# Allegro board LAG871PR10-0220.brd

Outline 317.5 x 114.3 mm; copper layers: TOP, GND1, IN1, GND2, IN2, IN3, VCC, IN4, GND3, BOTTOM. Coordinates in mm from the lower left corner of the outline.

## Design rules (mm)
net group 10: nets +MIC2-VREFO-L +MIC2-VREFO-R
net group ASYN_12: nets H_CPUPWRGD H_CPUPWRGD_R
net group BC BUS_12/15: nets BC_CLK_ECE1117 BC_DAT_ECE1117
net group DDRB_CKE: nets DDR_B_CKE0 DDR_B_CKE1
net group DIFFPAIR1: nets UPD1_SMBCLK UPD1_SMBDAT
net group ISH_I2C1_ALS_SCL: nets ISH_I2C1_ALS_SCL ISH_I2C1_ALS_SDA
net group ISUM_SA: nets ISUMN_SA ISUMP_SA
net group ISUMN_GT: nets ISUMN_GT ISUMP_GT
net group MIPI: nets WWAN_MIPI_ANT_CLK WWAN_MIPI_ANT_DAT
net group PCIE_PRX_C_DTX_9: nets PCIE_PRX_C_DTX_N9 PCIE_PRX_C_DTX_P9
net group PCIE_PRX_DTX_13: nets PCIE_PRX_DTX_N13 PCIE_PRX_DTX_P13
net group PCIE_PRX_DTX_14: nets PCIE_PRX_DTX_N14 PCIE_PRX_DTX_P14
net group PCIE_PRX_DTX_15: nets PCIE_PRX_DTX_N15 PCIE_PRX_DTX_P15
net group PCIE_PRX_DTX_16: nets PCIE_PRX_DTX_N16 PCIE_PRX_DTX_P16
net group PCIE_PTX_C_DRX_13: nets PCIE_PTX_C_DRX_N13 PCIE_PTX_C_DRX_P13
net group PCIE_PTX_C_DRX_14: nets PCIE_PTX_C_DRX_N14 PCIE_PTX_C_DRX_P14
net group PCIE_PTX_C_DRX_15: nets PCIE_PTX_C_DRX_N15 PCIE_PTX_C_DRX_P15
net group PCIE_PTX_C_SW_DRX_12: nets PCIE_PTX_C_DRX_N11 PCIE_PTX_C_DRX_P11
net group PCIE_PTX_DRX_13: nets PCIE_PTX_DRX_N13 PCIE_PTX_DRX_P13
net group PCIE_PTX_DRX_14: nets PCIE_PTX_DRX_N14 PCIE_PTX_DRX_P14
net group PCIE_PTX_DRX_15: nets PCIE_PTX_DRX_N15 PCIE_PTX_DRX_P15
net group PCIE_PTX_DRX_16: nets PCIE_PTX_DRX_N16 PCIE_PTX_DRX_P16
net group PECI: nets PECI_EC PECI_EC_R
net group RTC_RTCX_20_70: nets PCH_RTCX1 PCH_RTCX2
net group SATA: nets PCIE_PTX_C_DRX_N16 PCIE_PTX_C_DRX_P16
net group SENSE_25: nets VCCIO_SENSE VSSIO_SENSE
net group TS_I2C_SCL: nets TS_I2C_SCL TS_I2C_SDA
net group USB3_PRX_DTX_P4: nets USB3_PRX_DTX_N4 USB3_PRX_DTX_P4
net group USB20_9_FP: nets USB20_N9_FP USB20_P9_FP
net group 5: nets ESPI_ALERT# ESPI_CS# ESPI_IO0 ESPI_IO0_R ESPI_IO1 ESPI_IO1_R ESPI_IO2 ESPI_IO2_R ESPI_IO3 ESPI_IO3_R ESPI_RESET#
net group 15: nets ESPI_CLK ESPI_CLK_5105 PCH_RTCRST# SRTCRST# TBT_ROM_CLK TBTA_ROM_CLK_PD
net group AR-HDMI: nets AR_DP1_N0 AR_DP1_N1 AR_DP1_N2 AR_DP1_N3 AR_DP1_P0 AR_DP1_P1 AR_DP1_P2 AR_DP1_P3 HDMI_CLKN HDMI_CLKP HDMI_L_CLKN HDMI_L_CLKP HDMI_L_TX_N0 HDMI_L_TX_N1 HDMI_L_TX_N2 HDMI_L_TX_P0 HDMI_L_TX_P1 HDMI_L_TX_P2 HDMI_TX_N0 HDMI_TX_N1 HDMI_TX_N2 HDMI_TX_P0 HDMI_TX_P1 HDMI_TX_P2
net group ASYN-COMP: nets CFG_RCOMP CPU_POPIRCOMP EDP_COMP EDRAM_OPIO_RCOMP EMMC_RCOMP EOPIO_RCOMP PCH_POPIRCOMP PCIE_RCOMPN PCIE_RCOMPP SD_RCOMP SM_RCOMP0 SM_RCOMP1 SM_RCOMP2 USBCOMP
net group ASYNCHRONOUS: nets +DDR_VREF_B_DQ +DDR_VREF_CA DDR_DRAMRST# DDR_DRAMRST#_R H_CATERR# H_VCCST_PWRGD_XDP PCH_PLTRST# PCH_PLTRST#_AND PLTRST_TPM# PROCHOT# PROCHOT#_R PROCHOT#_R1 VCCST_PWRGD VCCST_PWRGD_CPU XDP_OBS0 XDP_OBS0_R XDP_OBS1 XDP_OBS1_R XDP_OBS2_R XDP_OBS3_R
net group CARD READER: nets SD/MMCDAT0/RCLK+ SD/MMCDAT0/RCLK+_R SD/MMCDAT1/RCLK- SD/MMCDAT1/RCLK-_R SD_UHS2_D0N SD_UHS2_D0P SD_UHS2_D1N SD_UHS2_D1P
net group CARD-S_12: nets SD/MMCCD# SD/MMCCLK SD/MMCCLK_R SD/MMCCMD SD/MMCCMD_R SD/MMCDAT2 SD/MMCDAT2_R SD/MMCDAT3 SD/MMCDAT3_R SDWP
net group CLK-S_15: nets CPU_XDP_TCLK DMIC_CLK0 HDA_BIT_CLK HDA_BIT_CLK_R JTAG_CLK MSCLK PCH_JTAG_TCK SUSCLK SUSCLK_R WIGIG_32KHZ XCLK_BIASREF XDP_JTAGX
net group CNV-SINGLE: nets CLKREQ_CNV# CNV_BRI_PRX_DTX CNV_BRI_PTX_DRX CNV_BRI_PTX_DRX_R CNV_COEX1 CNV_COEX2 CNV_COEX3 CNV_DET#_EC CNV_RF_RESET# CNV_RGI_PRX_DTX CNV_RGI_PTX_DRX CNV_RGI_PTX_DRX_R CNV_WT_RCOMP
net group CNVI: nets CLK_CNV_PRX_DTX_N CLK_CNV_PRX_DTX_P CLK_CNV_PTX_DRX_N CLK_CNV_PTX_DRX_P CNV_PRX_DTX_N0 CNV_PRX_DTX_N1 CNV_PRX_DTX_P0 CNV_PRX_DTX_P1 CNV_PTX_DRX_N0 CNV_PTX_DRX_N1 CNV_PTX_DRX_P0 CNV_PTX_DRX_P1
net group CODEC: nets AUD_HP_NB_SENSE AUD_HP_OUT_L AUD_HP_OUT_L1 AUD_HP_OUT_R AUD_HP_OUT_R1 AUD_SENSE_A HP_OUT_L HP_OUT_R INT_SPK_L+ INT_SPK_L- INT_SPK_R+ INT_SPK_R- INT_SPKR_L+ INT_SPKR_L- INT_SPKR_R+ INT_SPKR_R- RING2 RING2_R SLEEVE SLEEVE_R
net group CONTROL LINK: nets PCH_CL_CLK1 PCH_CL_DATA1 PCH_CL_RST1#
net group CRITICAL LOW: nets H_THERMTRIP# INTRUDER# PCH_DPWROK PCH_DPWROK_EC PCH_PCIE_WAKE# PCH_RSMRST# PCH_RSMRST#_AND RESET_OUT RESET_OUT#_R SIO_PWRBTN# SVID_ALERT#_PWR_CPU SVID_CLK_PWR_CPU SVID_DAT_PWR_CPU SYS_PWROK SYS_RESET# THERMTRIP2# XDP_DBRESET#
net group CRITICAL S_15: nets PCH_PWROK PCIE_WAKE# PCIE_WAKE#_R
net group DDI1: nets CPU_DP1_AUXN CPU_DP1_AUXN_C CPU_DP1_AUXP CPU_DP1_AUXP_C CPU_DP1_N0 CPU_DP1_N0_C CPU_DP1_N1 CPU_DP1_N1_C CPU_DP1_N2 CPU_DP1_N2_C CPU_DP1_N3 CPU_DP1_N3_C CPU_DP1_P0 CPU_DP1_P0_C CPU_DP1_P1 CPU_DP1_P1_C CPU_DP1_P2 CPU_DP1_P2_C CPU_DP1_P3 CPU_DP1_P3_C
net group DDI2: nets CPU_DP2_AUXN CPU_DP2_AUXN_C CPU_DP2_AUXP CPU_DP2_AUXP_C CPU_DP2_N0 CPU_DP2_N0_C CPU_DP2_N1 CPU_DP2_N1_C CPU_DP2_N2 CPU_DP2_N2_C CPU_DP2_N3 CPU_DP2_N3_C CPU_DP2_P0 CPU_DP2_P0_C CPU_DP2_P1 CPU_DP2_P1_C CPU_DP2_P2 CPU_DP2_P2_C CPU_DP2_P3 CPU_DP2_P3_C
net group DDRA-ALERT: nets DDR_A_ALERT#
net group DDRA-CLK: nets DDR_A_CLK0 DDR_A_CLK1 DDR_A_CLK#0 DDR_A_CLK#1
net group DDRA-CMD: nets DDR_A_ACT# DDR_A_BA0 DDR_A_BA1 DDR_A_BG0 DDR_A_BG1 DDR_A_MA0 DDR_A_MA1 DDR_A_MA2 DDR_A_MA3 DDR_A_MA4 DDR_A_MA5 DDR_A_MA6 DDR_A_MA7 DDR_A_MA8 DDR_A_MA9 DDR_A_MA10 DDR_A_MA11 DDR_A_MA12 DDR_A_MA13 DDR_A_MA14 DDR_A_MA15 DDR_A_MA16 DDR_A_PARITY
net group DDRA-CTL: nets DDR_A_CS#0 DDR_A_CS#1 DDR_A_ODT0 DDR_A_ODT1
net group DDRA-D0: nets DDR_A_D0 DDR_A_D1 DDR_A_D2 DDR_A_D3 DDR_A_D4 DDR_A_D5 DDR_A_D6 DDR_A_D7
net group DDRA-D1: nets DDR_A_D8 DDR_A_D9 DDR_A_D10 DDR_A_D11 DDR_A_D12 DDR_A_D13 DDR_A_D14 DDR_A_D15
net group DDRA-D2: nets DDR_A_D16 DDR_A_D17 DDR_A_D18 DDR_A_D19 DDR_A_D20 DDR_A_D21 DDR_A_D22 DDR_A_D23
net group DDRA-D3: nets DDR_A_D24 DDR_A_D25 DDR_A_D26 DDR_A_D27 DDR_A_D28 DDR_A_D29 DDR_A_D30 DDR_A_D31
net group DDRA-D4: nets DDR_A_D32 DDR_A_D33 DDR_A_D34 DDR_A_D35 DDR_A_D36 DDR_A_D37 DDR_A_D38 DDR_A_D39
net group DDRA-D5: nets DDR_A_D40 DDR_A_D41 DDR_A_D42 DDR_A_D43 DDR_A_D44 DDR_A_D45 DDR_A_D46 DDR_A_D47
net group DDRA-D6: nets DDR_A_D48 DDR_A_D49 DDR_A_D50 DDR_A_D51 DDR_A_D52 DDR_A_D53 DDR_A_D54 DDR_A_D55
net group DDRA-D7: nets DDR_A_D56 DDR_A_D57 DDR_A_D58 DDR_A_D59 DDR_A_D60 DDR_A_D61 DDR_A_D62 DDR_A_D63
net group DDRA-DQS: nets DDR_A_DQS0 DDR_A_DQS1 DDR_A_DQS2 DDR_A_DQS3 DDR_A_DQS4 DDR_A_DQS5 DDR_A_DQS6 DDR_A_DQS7 DDR_A_DQS#0 DDR_A_DQS#1 DDR_A_DQS#2 DDR_A_DQS#3 DDR_A_DQS#4 DDR_A_DQS#5 DDR_A_DQS#6 DDR_A_DQS#7
net group DDRA_CKE: nets DDR_A_CKE0 DDR_A_CKE1 DDR_A_CKE2 DDR_A_CKE3
net group DDRB-CLK: nets DDR_B_CLK0 DDR_B_CLK1 DDR_B_CLK#0 DDR_B_CLK#1
net group DDRB-CMD: nets DDR_B_ACT# DDR_B_BA0 DDR_B_BA1 DDR_B_BG0 DDR_B_BG1 DDR_B_MA0 DDR_B_MA1 DDR_B_MA2 DDR_B_MA3 DDR_B_MA4 DDR_B_MA5 DDR_B_MA6 DDR_B_MA7 DDR_B_MA8 DDR_B_MA9 DDR_B_MA10 DDR_B_MA11 DDR_B_MA12 DDR_B_MA13 DDR_B_MA14 DDR_B_MA15 DDR_B_MA16 DDR_B_PARITY
net group DDRB-CTL: nets DDR_B_CS#0 DDR_B_CS#1 DDR_B_ODT0 DDR_B_ODT1
net group DDRB-D0: nets DDR_B_D0 DDR_B_D1 DDR_B_D2 DDR_B_D3 DDR_B_D4 DDR_B_D5 DDR_B_D6 DDR_B_D7
net group DDRB-D1: nets DDR_B_D8 DDR_B_D9 DDR_B_D10 DDR_B_D11 DDR_B_D12 DDR_B_D13 DDR_B_D14 DDR_B_D15
net group DDRB-D2: nets DDR_B_D16 DDR_B_D17 DDR_B_D18 DDR_B_D19 DDR_B_D20 DDR_B_D21 DDR_B_D22 DDR_B_D23
net group DDRB-D3: nets DDR_B_D24 DDR_B_D25 DDR_B_D26 DDR_B_D27 DDR_B_D28 DDR_B_D29 DDR_B_D30 DDR_B_D31
net group DDRB-D4: nets DDR_B_D32 DDR_B_D33 DDR_B_D34 DDR_B_D35 DDR_B_D36 DDR_B_D37 DDR_B_D38 DDR_B_D39
net group DDRB-D5: nets DDR_B_D40 DDR_B_D41 DDR_B_D42 DDR_B_D43 DDR_B_D44 DDR_B_D45 DDR_B_D46 DDR_B_D47
net group DDRB-D6: nets DDR_B_D48 DDR_B_D49 DDR_B_D50 DDR_B_D51 DDR_B_D52 DDR_B_D53 DDR_B_D54 DDR_B_D55
net group DDRB-D7: nets DDR_B_D56 DDR_B_D57 DDR_B_D58 DDR_B_D59 DDR_B_D60 DDR_B_D61 DDR_B_D62 DDR_B_D63
net group DDRB-DQS: nets DDR_B_DQS0 DDR_B_DQS1 DDR_B_DQS2 DDR_B_DQS3 DDR_B_DQS4 DDR_B_DQS5 DDR_B_DQS6 DDR_B_DQS7 DDR_B_DQS#0 DDR_B_DQS#1 DDR_B_DQS#2 DDR_B_DQS#3 DDR_B_DQS#4 DDR_B_DQS#5 DDR_B_DQS#6 DDR_B_DQS#7
net group DDRB_ALERT: nets DDR_B_ALERT#
net group DIRTY_POWER: nets +13.2VB_BATT +13.2VB_PBATT_C +13.5VB_1.05VALWP +13.5VB_3V +13.5VB_CPU +13.5VB_DDR +13.5VB_VCCSA +13.5VB_VCHGR +19.5V_AC +19.5V_DC_IN +19.5V_DC_IN_SS +19.5V_SDC_IN +20V_VBUS_DC_SS LG1_CHG LG2_CHG LG_SA LX1_CHG LX1_IA LX2_CHG LX2_IA LX_1.05VALWP LX_1.8VALW LX_1V_PRIM_CORE LX_1VS_VCCIO LX_3V LX_DDR LX_GT LX_SA PWM1_IA PWM2_IA PWM_A_GT PWM_GT SNUB1_CHG SNUB1_IA SNUB2_CHG SNUB2_IA SNUB_1.05VALWP SNUB_1.8VALW SNUB_1V_PRIM_CORE SNUB_1VS_VCCIO SNUB_3V SNUB_5V SNUB_DDR SNUB_GT SNUB_SA UG1_CHG UG2_CHG UG_SA VIN_1.8VALW VIN_1V_PRIM_CORE VIN_1VS_VCCIO
net group EDP: nets EDP_AUXN EDP_AUXN_C EDP_AUXP EDP_AUXP_C EDP_TXN0 EDP_TXN0_C EDP_TXN1 EDP_TXN1_C EDP_TXP0 EDP_TXP0_C EDP_TXP1 EDP_TXP1_C
net group EMI: nets BIA_PWM BIA_PWM_EC BST_3V BST_5V EDP_BIA_PWM HOST_DEBUG_TX
net group ESD-GND: nets CPU_XDP_PRDY# CPU_XDP_PREQ# CPU_XDP_TDI CPU_XDP_TDO CPU_XDP_TMS CPU_XDP_TRST# PCH_JTAG_TDI PCH_JTAG_TDO PCH_JTAG_TMS POWER_SW#_MB POWER_SW_IN# RUNPWROK SIO_SLP_A#
net group ESD-NOCROSS-MOAT: nets CFG0 CFG1 CFG2 CFG3 CFG4 CFG5 CFG6 CFG7 CFG8 CFG9 CFG10 CFG11 CFG12 CFG13 CFG14 CFG15 CFG16 CFG17 CFG18 CFG19 ITP_PMODE PROCHOT#_CHG USB_OC3#
net group GREENCLK_20: nets MEC_XTAL1 MEC_XTAL2 MEC_XTAL2_R XTAL_25_IN XTAL_25_OUT XTAL_25_OUT_R
net group HDA_5_15: nets DMIC0 HDA_RST# HDA_RST#_R HDA_SDIN0 HDA_SDIN0_R HDA_SDOUT HDA_SDOUT_R HDA_SYNC HDA_SYNC_R
net group I2C_15: nets ISH_I2C2_SCL ISH_I2C2_SCL_R ISH_I2C2_SDA ISH_I2C2_SDA_R
net group MSDATA: nets MSDATA
net group OTHERS SINGLE-END: nets BAT1_LED# BAT2_LED# BATT_WHITE# BATT_YELLOW#
net group PCIE-AR: nets PCIE_PRX_C_DTX_N5 PCIE_PRX_C_DTX_N6 PCIE_PRX_C_DTX_N7 PCIE_PRX_C_DTX_N8 PCIE_PRX_C_DTX_P5 PCIE_PRX_C_DTX_P6 PCIE_PRX_C_DTX_P7 PCIE_PRX_C_DTX_P8 PCIE_PRX_DTX_N5 PCIE_PRX_DTX_N6 PCIE_PRX_DTX_N7 PCIE_PRX_DTX_N8 PCIE_PRX_DTX_P5 PCIE_PRX_DTX_P6 PCIE_PRX_DTX_P7 PCIE_PRX_DTX_P8 PCIE_PTX_C_DRX_N5 PCIE_PTX_C_DRX_N6 PCIE_PTX_C_DRX_N7 PCIE_PTX_C_DRX_N8 PCIE_PTX_C_DRX_P5 PCIE_PTX_C_DRX_P6 PCIE_PTX_C_DRX_P7 PCIE_PTX_C_DRX_P8 PCIE_PTX_DRX_N5 PCIE_PTX_DRX_N6 PCIE_PTX_DRX_N7 PCIE_PTX_DRX_N8 PCIE_PTX_DRX_P5 PCIE_PTX_DRX_P6 PCIE_PTX_DRX_P7 PCIE_PTX_DRX_P8
net group PCIE-CR: nets PCIE_PRX_DTX_N9 PCIE_PRX_DTX_P9 PCIE_PTX_C_DRX_N9 PCIE_PTX_C_DRX_P9 PCIE_PTX_DRX_N9 PCIE_PTX_DRX_P9
net group PCIE-LTE/SATA/USB: nets PCIE_PRX_DTX_N11 PCIE_PRX_DTX_N12 PCIE_PRX_DTX_P11 PCIE_PRX_DTX_P12 PCIE_PRX_L_DTX_N11 PCIE_PRX_L_DTX_P11 PCIE_PRX_SW_DTX_N11 PCIE_PRX_SW_DTX_P11 PCIE_PTX_C_DRX_N12 PCIE_PTX_C_DRX_P12 PCIE_PTX_DRX_N11 PCIE_PTX_DRX_N12 PCIE_PTX_DRX_P11 PCIE_PTX_DRX_P12 PCIE_PTX_L_DRX_N11 PCIE_PTX_L_DRX_P11 PCIE_PTX_SW_DRX_N11 PCIE_PTX_SW_DRX_P11
net group PCIE-WLAN: nets PCIE_PRX_DTX_N10 PCIE_PRX_DTX_P10 PCIE_PTX_C_DRX_N10 PCIE_PTX_C_DRX_P10 PCIE_PTX_DRX_N10 PCIE_PTX_DRX_P10
net group PLATFORM CLK: nets CLK_ITPXDP_N CLK_ITPXDP_N_R CLK_ITPXDP_P CLK_ITPXDP_P_R CLK_PCIE_N0 CLK_PCIE_N1 CLK_PCIE_N2 CLK_PCIE_N4 CLK_PCIE_N5 CLK_PCIE_P0 CLK_PCIE_P1 CLK_PCIE_P2 CLK_PCIE_P4 CLK_PCIE_P5 CLKREQ_PCIE#0 CLKREQ_PCIE#0_R CLKREQ_PCIE#1 CLKREQ_PCIE#1_R CLKREQ_PCIE#2 CLKREQ_PCIE#2_R CLKREQ_PCIE#4 CLKREQ_PCIE#4_R CLKREQ_PCIE#5 CLKREQ_PCIE#5_R REFCLK_CNV XTAL24_IN XTAL24_IN_CPU XTAL24_OUT_CPU
net group SD-NOCROSS-MOAT: nets JTAG_RST# USB_OC0# USB_OC1# USB_OC2#
net group SIM_15: nets UIM_CLK UIM_DATA UIM_RESET
net group SMB_15: nets CLK_TP_SIO_I2C_DAT CLK_TP_SIO_R CPU_DP1_CTRL_CLK CPU_DP1_CTRL_DATA CPU_DP2_CTRL_CLK CPU_DP2_CTRL_DATA DDR_XDP_WAN_SMBCLK DDR_XDP_WAN_SMBDAT HDMI_CTRL_CLK HDMI_CTRL_DATA PBAT_SMBCLK_C PBAT_SMBDAT_C
net group SMBUS: nets TBT_I2C_SCL TBT_I2C_SDA UPD1_SMBINT# UPD1_SMBINT#_R
net group SPI: nets PCH_SPI_CLK PCH_SPI_CLK_0_R PCH_SPI_CLK_1_R PCH_SPI_CLK_2_R PCH_SPI_CLK_R1 PCH_SPI_CS#0 PCH_SPI_CS#0_R1 PCH_SPI_CS#0_R2 PCH_SPI_CS#1 PCH_SPI_CS#1_R1 PCH_SPI_CS#1_R2 PCH_SPI_CS#2 PCH_SPI_CS#2_R PCH_SPI_D0 PCH_SPI_D0_0_R PCH_SPI_D0_1_R PCH_SPI_D0_2_R PCH_SPI_D0_R1 PCH_SPI_D1 PCH_SPI_D1_0_R PCH_SPI_D1_1_R PCH_SPI_D1_2_R PCH_SPI_D1_R1 PCH_SPI_D2 PCH_SPI_D2_0_R PCH_SPI_D2_1_R PCH_SPI_D2_R1 PCH_SPI_D3 PCH_SPI_D3_0_R PCH_SPI_D3_1_R PCH_SPI_D3_R1 PCH_SPI_DO2_XDP PCH_SPI_DO_XDP
net group SVID: nets H_CPU_SVIDALRT# VIDALERT_N VIDSCLK VIDSCLK_R VIDSOUT VIDSOUT_R
net group TBT-AR: nets TBTA_AUXN TBTA_AUXP TBTA_BOT_N TBTA_BOT_P TBTA_DEBUG3 TBTA_DEBUG4 TBTA_LSRX TBTA_LSTX TBTA_TOP_N TBTA_TOP_P TBTA_USB20_N TBTA_USB20_N_R TBTA_USB20_P TBTA_USB20_P_R
net group THERMAL: nets REM_DIODE1_N REM_DIODE1_P REM_DIODE2_N REM_DIODE2_P REM_DIODE4_N REM_DIODE4_P
net group THUNDERBOLT: nets TBT_A_TRX_C_DTX_N0 TBT_A_TRX_C_DTX_N1 TBT_A_TRX_C_DTX_P0 TBT_A_TRX_C_DTX_P1 TBT_A_TRX_DTX_N0 TBT_A_TRX_DTX_N1 TBT_A_TRX_DTX_P0 TBT_A_TRX_DTX_P1 TBT_A_TRX_R_DTX_N0 TBT_A_TRX_R_DTX_N1 TBT_A_TRX_R_DTX_P0 TBT_A_TRX_R_DTX_P1 TBT_A_TTX_C_DRX_N0 TBT_A_TTX_C_DRX_N1 TBT_A_TTX_C_DRX_P0 TBT_A_TTX_C_DRX_P1 TBT_A_TTX_DRX_N0 TBT_A_TTX_DRX_N1 TBT_A_TTX_DRX_P0 TBT_A_TTX_DRX_P1 TBT_A_TTX_R_DRX_N0 TBT_A_TTX_R_DRX_N1 TBT_A_TTX_R_DRX_P0 TBT_A_TTX_R_DRX_P1
net group USB2.0: nets SW_USB20_N2 SW_USB20_P2 USB20_N1 USB20_N2 USB20_N2_R USB20_N3 USB20_N3_R USB20_N6 USB20_N6_R USB20_N7 USB20_N7_L USB20_N8 USB20_N9 USB20_N9_USH USB20_N10 USB20_N10_R USB20_P1 USB20_P2 USB20_P2_R USB20_P3 USB20_P3_R USB20_P6 USB20_P6_R USB20_P7 USB20_P7_L USB20_P8 USB20_P9 USB20_P9_USH USB20_P10 USB20_P10_R
net group USB3.0: nets USB3_PRX_DTX_N2 USB3_PRX_DTX_P2 USB3_PTX_C_DRX_N2 USB3_PTX_C_DRX_N3 USB3_PTX_C_DRX_N4 USB3_PTX_C_DRX_P2 USB3_PTX_C_DRX_P3 USB3_PTX_C_DRX_P4 USB3_PTX_DRX_N2 USB3_PTX_DRX_N4 USB3_PTX_DRX_P2 USB3_PTX_DRX_P4
nets with their own width: min track width 0.254; nets +1.2V_MEM +5V_ALWP N17371029
nets with their own width: min track width 0.381; nets +1.8V_ANT_R +2.7V_ANT_R +20V_LDO_INPUT +SDREG2 TBTA_CC1 TBTA_CC2
nets with their own width: min track width 0.508; nets +1.0V_AMPHYPLL +1.0V_APLL +1.0V_CLK +1.0V_PRIM_XDP +1.0V_VCCST +1.0V_VCCST_C +1.0V_VCCSTG +1.0V_VCCSTG_C +1.2V_LDO +1.8V_ANT +1.8V_RUN_CARD +2.7V_ANT +3.3V_ALW +3.3V_ALW2 +3.3V_ALW_DSW +3.3V_ALW_UE1 +3.3V_ALWP +3.3V_CAM +3.3V_FPBTN +3.3V_MMI_AUX +3.3V_RTC_LDO +3.3V_RUN_AUDIO +3.3V_RUN_AUDIO_DVDD +3.3V_RUN_AUDIO_IO +3.3V_RUN_AUDIO_UZ5 +3.3V_SPI +3.3V_TP +5V_ALW +5V_ALW2 +20V_TBTA_VBUS_1 +COINCELL +DDR_VREF_A_CA +DDR_VREF_B_CA +PECI_VREF +RTC_CELL +RTC_CELL_PCH +RTC_CELL_VBAT +SIM_PWR +VCC_CORE +VCC_CORE_G0 +VCC_CORE_G1 +VCC_GT +VCCPDSW_1P05 +VCCPLL_OC +VDDA_AVDD1 +VR_CAP +Z4012 BST_SA_R GND GNDA N29478750 N29478753 VCCHDA
nets with their own width: min track width 0.762; nets +2.5V_MEM +3.3V_TBT_SX +3.3V_VDD_PIC_R
nets with their own width: min track width 1.016; nets +0.6V_DDR_VTT +1.8V_PRIM +1.8V_RUN +1.8V_RUN_UZ8 +3.3V_ALW_PCH +3.3V_ALW_PCH_UZ3 +3.3V_RUN_CARD +TS_PWR +VHDMI_VCC
nets with their own width: min track width 1.27; nets +3.3V_MMI_IN
nets with their own width: min track width 1.524; nets +EDP_VDD +LCDVDD
nets with their own width: min track width 2.032; nets +BL_PWR_SRC +USB_EX2_PWR
nets with their own width: min track width 2.286; nets +3.3V_HDD_M2 +3.3V_WLAN +3.3V_WLAN_UZ47
nets with their own width: min track width 2.54; nets +5V_RUN +5V_RUN_AUDIO +5V_RUN_AUDIO_UZ5 +5V_RUN_PVDD_L +5V_RUN_UZ47 +5V_USB_CHG_PWR
nets with their own width: min track width 2.794; nets +1.0V_PRIM_CORE +3.3V_WWAN +3.3V_WWAN_UZ43
nets with their own width: min track width 3.048; nets +1.0V_MPHYGT
nets with their own width: min track width 3.302; nets +1.0VS_VCCIO
nets with their own width: min track width 3.556; nets +3.3V_RUN +3.3V_RUN_UZ3 +5V_ALW_PDA
nets with their own width: min track width 6.858; nets +1.0V_PRIM

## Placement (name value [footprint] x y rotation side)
CA1  680P_0402_50V7K  [C_0402]  308.82 46.41 180 top
CA2  680P_0402_50V7K  [C_0402]  298.27 35.6 90 top
CA3  680P_0402_50V7K  [C_0402]  298.27 38.3 270 top
CA4  680P_0402_50V7K  [C_0402]  301.12 45.54 270 top
CA5  100P_0402_50V8J  [C_0402]  58.68 105.96 90 top
CA6  82P_0402_50V8J  [C_0402]  56.6 106.81 180 top
CA7  0.1U_0201_10V6K  [C_0201]  54.99 109.57 180 top
CA8  0.1U_0201_10V6K  [C_0201]  283.08 44.98 90 top
CA9  10U_0603_10V6M  [C_0603]  284.36 47.56 90 top
CA10  0.1U_0201_10V6K  [C_0201]  276.74 41.93 90 top
CA12  680P_0402_50V7K  [C_0402]  306.46 47.03 90 top
CA13  680P_0402_50V7K  [C_0402]  302.08 47.38 270 top
CA19  1000P_0402_50V7K  [C_0402]  278.76 46.4 90 top
CA22  1000P_0402_50V7K  [C_0402]  281.44 46.4 90 top
CA23  1000P_0402_50V7K  [C_0402]  280.54 46.4 90 top
CA24  1000P_0402_50V7K  [C_0402]  279.65 46.4 90 top
CA25  10U_0603_10V6M  [C_0603]  290.33 40.76 0 top
CA27  0.1U_0402_25V6  [C_0402]  285.85 57.23 270 top
CA28  0.1U_0402_25V6  [C_0402]  286.73 57.23 270 top
CA29  1U_0201_6.3V6K  [C_0201]  284.03 36.2 0 top
CA31  1U_0201_6.3V6M  [C_0201]  277.03 43.11 180 top
CA33  10P_0402_50V8J  [C_0402]  274.94 37.24 90 top
CA35  2.2U_0402_6.3V6M  [C_0402]  283.98 44.77 90 top
CA41  0.1U_0402_25V6  [C_0402]  276.37 44.67 180 top
CA43  10U_0603_10V6M  [C_0603]  285.02 46.29 270 top
CA44  10U_0603_10V6M  [C_0603]  286.21 46.29 270 top
CA45  0.1U_0201_10V6K  [C_0201]  282.16 46.76 90 top
CA46  10U_0603_10V6M  [C_0603]  281.06 48.51 180 top
CA47  0.1U_0201_10V6K  [C_0201]  277.48 46.35 180 top
CA48  10U_0603_10V6M  [C_0603]  277.69 47.36 180 top
CA49  1U_0201_6.3V6K  [C_0201]  285.59 36.76 0 top
CA51  10U_0603_10V6M  [C_0603]  285.63 47.56 90 top
CA52  10U_0603_10V6M  [C_0603]  287.66 34.73 0 top
CA53  10U_0603_10V6M  [C_0603]  280.67 34.8 270 top
CA54  100P_0402_50V8J  [C_0402]  275.84 38.79 0 top
CA55  0.1U_0201_10V6K  [C_0201]  279.38 35.6 180 top
CA56  10U_0603_10V6M  [C_0603]  279.41 34.8 270 top
CA57  0.1U_0201_10V6K  [C_0201]  282.61 35.62 0 top
CA58  10U_0603_10V6M  [C_0603]  287.03 33.52 0 top
CA59  10U_0603_10V6M  [C_0603]  278.52 50.92 270 top
CA60  0.1U_0201_10V6K  [C_0201]  281.31 50.96 270 top
CA61  10U_0603_10V6M  [C_0603]  275.65 42.21 180 top
CA62  100P_0402_50V8J  [C_0402]  287.41 58.08 90 top
CA63  12P_0402_50V8J  [C_0402]  279.61 50.82 270 top
CA64  68P_0402_50V8J  [C_0402]  280.52 50.82 270 top
CA65  12P_0402_50V8J  [C_0402]  281.2 32.44 180 top
CA66  68P_0402_50V8J  [C_0402]  281.2 31.49 180 top
CA67  12P_0402_50V8J  [C_0402]  279.34 32.46 270 top
CA68  68P_0402_50V8J  [C_0402]  278.39 32.46 270 top
CA69  33P_0402_50V8J  [C_0402]  281.88 34.49 270 top
CA72  100P_0402_50V8J  [C_0402]  283.85 56.31 90 top
CA73  330P_0402_50V8J  [C_0402]  287.6 36.71 270 top
CA74  330P_0402_50V8J  [C_0402]  286.52 37.83 90 top
CA76  1U_0201_6.3V6K  [C_0201]  284.03 35.63 0 top
CA77  1U_0201_6.3V6K  [C_0201]  285.59 36.16 0 top
CC9  0.1U_0201_10V6K  [C_0201]  188.4 59.92 180 top
CC10  0.1U_0201_10V6K  [C_0201]  198.21 66.73 0 bottom
CC21  15P_0402_50V8J  [C_0402]  157.05 96.26 180 bottom
CC22  15P_0402_50V8J  [C_0402]  157.05 94.42 180 bottom
CC23  15P_0402_50V8J  [C_0402]  151.68 57.92 270 top
CC24  1U_0201_6.3V6M  [C_0201]  151.29 54.17 270 top
CC25  1U_0201_6.3V6M  [C_0201]  153.13 53.85 270 top
CC26  15P_0402_50V8J  [C_0402]  153.21 59.42 90 top
CC27  47P_0402_50V8J  [C_0402]  148.66 52.14 270 top
CC28  1U_0201_6.3V6M  [C_0201]  140.1 95.13 180 top
CC29  1U_0201_6.3V6M  [C_0201]  137.99 95.31 180 bottom
CC31  1U_0201_6.3V6M  [C_0201]  142.67 86.47 0 top
CC32  22U_0603_6.3V6M  [C_0603]  120.93 57.77 180 top
CC33  10U_0402_6.3V6M  [C_0402]  132.8 64.32 270 top
CC34  10U_0402_6.3V6M  [C_0402]  128.39 64.04 270 top
CC35  10U_0402_6.3V6M  [C_0402]  136.36 62.29 270 top
CC36  10U_0402_6.3V6M  [C_0402]  136.33 63.48 90 top
CC37  10U_0402_6.3V6M  [C_0402]  121.2 63.61 180 top
CC38  10U_0402_6.3V6M  [C_0402]  139.15 64.24 270 top
CC39  10U_0402_6.3V6M  [C_0402]  138.54 75.11 180 top
CC40  10U_0402_6.3V6M  [C_0402]  138.54 76 180 top
CC41  10U_0402_6.3V6M  [C_0402]  139.36 80.75 180 top
CC42  10U_0402_6.3V6M  [C_0402]  126.41 75.11 180 top
CC45  10U_0402_6.3V6M  [C_0402]  124.73 59.49 0 top
CC46  10U_0402_6.3V6M  [C_0402]  124.73 58.6 0 top
CC51  10U_0402_6.3V6M  [C_0402]  139.36 81.64 180 top
CC52  10U_0402_6.3V6M  [C_0402]  141.06 81.89 90 top
CC65  1U_0201_6.3V6M  [C_0201]  145.74 76.97 225 top
CC66  1U_0201_6.3V6M  [C_0201]  147.52 83.42 270 top
CC67  1U_0201_6.3V6M  [C_0201]  143.68 80.05 0 top
CC68  1U_0201_6.3V6M  [C_0201]  143.68 80.63 0 top
CC69  1U_0201_6.3V6M  [C_0201]  143.76 93.83 0 bottom
CC70  1U_0201_6.3V6M  [C_0201]  161.4 94.66 90 bottom
CC71  22U_0603_6.3V6M  [C_0603]  162.46 84.42 0 top
CC72  0.1U_0201_6.3V6K  [C_0201]  141.75 77.55 90 top
CC73  1U_0201_6.3V6M  [C_0201]  150.63 52.27 0 top
CC75  1U_0201_6.3V6M  [C_0201]  164.04 74.23 180 bottom
CC76  1U_0201_6.3V6M  [C_0201]  140.93 76.65 90 top
CC77  2.2P_0201_25V  [C_0201]  168.79 78.71 270 top
CC78  0.1U_0402_25V6  [C_0402]  174.39 89.34 0 top
CC80  1U_0201_6.3V6M  [C_0201]  143.76 93.24 0 bottom
CC83  1U_0201_6.3V6M  [C_0201]  161.97 94.66 90 bottom
CC84  4.7U_0402_6.3V6M  [C_0402]  162.19 74.49 270 bottom
CC85  22U_0603_6.3V6M  [C_0603]  145.29 101.17 0 top
CC86  22U_0603_6.3V6M  [C_0603]  144.93 95.4 180 top
CC93  0.1U 16V K X5R 0201  [C_0201]  154.63 54.95 90 top
CC95  2.2P_0201_25V  [C_0201]  166.69 79.09 270 top
CC96  22U_0603_6.3V6M  [C_0603]  141.73 96.67 180 top
CC98  1U_0201_6.3V6M  [C_0201]  147.77 79.69 180 top
CC100  22U_0603_6.3V6M  [C_0603]  162.85 94.51 90 bottom
CC102  22U_0603_6.3V6M  [C_0603]  147.52 98.42 90 top
CC103  22U_0603_6.3V6M  [C_0603]  164.06 94.51 90 bottom
CC104  22U_0603_6.3V6M  [C_0603]  147.52 97.28 0 top
CC195  1U_0201_6.3V6M  [C_0201]  116.26 64.62 0 top
CC196  .047U_0402_16V7K  [C_0402]  193.89 72.05 90 top
CC234  10U_0402_6.3V6M  [C_0402]  138.58 79.28 180 top
CC235  10U_0402_6.3V6M  [C_0402]  137.71 77.5 90 top
CC236  10U_0402_6.3V6M  [C_0402]  140.2 80.5 0 top
CC237  10U_0402_6.3V6M  [C_0402]  124.63 75.14 180 top
CC266  0.01UF_0402_25V7K  [C_0402]  165.96 56.52 270 top
CC269  0.1U_0201_25V6K  [C_0201]  62.34 95.12 0 top
CC279  22U_0402_6.3V6M  [C_0402]  166.46 63.59 90 top
CC280  22U_0402_6.3V6M  [C_0402]  165.26 63.59 90 top
CC288  0.1U_0201_10V6K  [C_0201]  86.32 107.4 90 top
CC299  0.1U_0201_10V6K  [C_0201]  61.28 96.35 90 top
CC300  100P_0402_50V8J  [C_0402]  130.24 95.51 270 bottom
CC301  100P_0402_50V8J  [C_0402]  136.69 99.48 90 bottom
CC302  0.1U_0402_25V6  [C_0402]  162.36 84.58 0 bottom
CC303  0.1U_0201_25V6K  [C_0201]  101.82 97.4 0 top
CC304  0.1U_0201_25V6K  [C_0201]  102.6 95.18 180 top
CC305  0.1U_0201_25V6K  [C_0201]  104.44 95.75 180 top
CC306  0.1U_0201_25V6K  [C_0201]  59.32 101.57 270 top
CC307  0.1U_0201_25V6K  [C_0201]  62.5 96.37 0 top
CC316  33P_0402_50V8J  [C_0402]  160.37 59.44 90 top
CC318  33P_0402_50V8J  [C_0402]  169.12 83.5 180 bottom
CC319  33P_0402_50V8J  [C_0402]  162.74 82.04 0 bottom
CC320  33P_0402_50V8J  [C_0402]  171.73 79.6 180 bottom
CC326  0.1U_0201_25V6K  [C_0201]  59.95 99.33 90 top
CC331  2.2P_0402_50V8C  [C_0402]  144.11 52.94 90 top
CC332  2.2P_0402_50V8C  [C_0402]  145.06 52.94 90 top
CC333  2.2P_0402_50V8C  [C_0402]  146.02 52.94 90 top
CC334  0.1U_0201_25V6K  [C_0201]  60.08 96.41 90 top
CC340  0.1U_0402_25V6K  [C_0402]  174.2 63.3 0 top
CC430  1U_0201_6.3V6M  [C_0201]  140.62 63.74 180 top
CC1452  33P_0402_50V8J  [C_0402]  193.16 72.19 0 bottom
CC1453  33P_0402_50V8J  [C_0402]  188.79 65.07 90 top
CC1454  10U_0402_6.3V6M  [C_0402]  121.2 64.5 180 top
CC1455  1U_0201_6.3V6M  [C_0201]  123.53 61.06 270 top
CC1456  1U_0201_6.3V6M  [C_0201]  122.93 75.06 90 top
CC1457  1U_0201_6.3V6M  [C_0201]  123.53 64.54 270 top
CC1458  1U_0201_6.3V6M  [C_0201]  138.68 80.02 180 top
CC1459  1U_0201_6.3V6M  [C_0201]  138.44 77.93 90 top
CC1460  1U_0201_6.3V6M  [C_0201]  125.1 75.88 180 top
CC1461  1U_0201_6.3V6M  [C_0201]  126.49 75.88 180 top
CC1462  0.1U_0201_10V6K  [C_0201]  141.8 84.8 270 top
CC1463  1U_0201_6.3V6M  [C_0201]  143.6 75.94 270 top
CC1464  1U_0201_6.3V6M  [C_0201]  160.09 79.38 270 top
CC1465  0.33U_0402_10V6K  [C_0402]  169.51 56.48 270 top
CC1466  100P_0201_50V8J  [C_0201]  106.48 111.73 90 top
CC1467  0.33U_0402_10V6K  [C_0402]  160.49 56.52 270 top
CC1468  0.33U_0402_10V6K  [C_0402]  145.97 55.81 180 top
CC1469  0.33U_0402_10V6K  [C_0402]  162.27 56.52 270 top
CC1470  0.33U_0402_10V6K  [C_0402]  164.05 56.52 270 top
CC1471  0.33U_0402_10V6K  [C_0402]  158.77 58.16 180 top
CC1476  33P_0402_50V8J  [C_0402]  167.95 76.64 0 bottom
CC1477  4.7P_0402_50V8C  [C_0402]  153.41 95.31 0 top
CC1478  1200P_0402_50V7K  [C_0402]  134.63 61.28 270 top
CC1479  680P_0402_50V7K  [C_0402]  117.79 75.18 0 top
CC1480  0.1U_0201_10V6K  [C_0201]  139.45 75.01 90 top
CD1  10U_0603_10V6M  [C_0603]  94.62 40.25 90 top
CD2  10U_0603_10V6M  [C_0603]  87.13 39.77 270 top
CD3  10U_0603_10V6M  [C_0603]  86.75 31.49 90 top
CD4  10U_0603_10V6M  [C_0603]  91.94 30.68 90 top
CD5  10U_0603_10V6M  [C_0603]  94.41 39.17 270 top
CD6  10U_0603_10V6M  [C_0603]  96.83 40.49 90 top
CD7  10U_0603_10V6M  [C_0603]  96.82 39.46 270 top
CD8  10U_0603_10V6M  [C_0603]  90.62 30.66 90 top
CD9  1U_0201_6.3V6M  [C_0201]  65.48 39.34 270 top
CD10  1U_0201_6.3V6M  [C_0201]  86.05 38.74 270 top
CD11  1U_0201_6.3V6M  [C_0201]  85.12 38.73 270 top
CD12  1U_0201_6.3V6M  [C_0201]  119.25 40.38 0 top
CD13  1U_0201_6.3V6M  [C_0201]  88.92 32.34 90 top
CD14  1U_0201_6.3V6M  [C_0201]  75.92 38.63 270 top
CD15  1U_0201_6.3V6M  [C_0201]  108.45 39.92 0 top
CD16  1U_0201_6.3V6M  [C_0201]  93.67 31.11 90 top
CD17  220U_D7_2VM_R4.5M  [C_D7]  115.18 44.3 180 top
CD18  1U_0201_6.3V6M  [C_0201]  123.78 39.04 270 top
CD19  1U_0201_6.3V6M  [C_0201]  125.31 39.04 270 top
CD20  10U_0603_10V6M  [C_0603]  124.09 40.44 90 top
CD21  10U_0603_10V6M  [C_0603]  125.31 40.44 90 top
CD22  10U_0603_10V6M  [C_0603]  125.31 32.43 90 top
CD23  1U_0201_6.3V6M  [C_0201]  123.28 33.03 90 top
CD24  1U_0201_6.3V6M  [C_0201]  123.28 31.44 270 top
CD25  0.1U_0201_6.3V6K  [C_0201]  100.48 30.65 90 top
CD26  2.2U_0402_6.3V6M  [C_0402]  101.42 30.65 90 top
CD27  2.2U_0402_6.3V6M  [C_0402]  122.04 41.97 0 top
CD28  0.1U_0201_10V6K  [C_0201]  122.38 41.21 0 top
CD29  0.1U_0402_25V6  [C_0402]  83.51 31.1 90 top
CD31  0.022U_0402_16V7K  [C_0402]  102.39 27.27 90 top
CD32  0.1U_0201_10V6K  [C_0201]  91.82 67.35 180 bottom
CD33  10U_0603_10V6M  [C_0603]  153.25 38.27 90 top
CD34  10U_0603_10V6M  [C_0603]  176.16 41.21 90 top
CD35  10U_0603_10V6M  [C_0603]  195.97 39.87 270 top
CD36  10U_0603_10V6M  [C_0603]  193 31.88 270 top
CD37  10U_0603_10V6M  [C_0603]  157.57 32.05 90 top
CD38  10U_0603_10V6M  [C_0603]  160.55 30.71 180 top
CD39  10U_0603_10V6M  [C_0603]  167.91 30.47 90 top
CD40  10U_0603_10V6M  [C_0603]  174.5 41.21 90 top
CD41  1U_0201_6.3V6M  [C_0201]  170.43 41.33 0 top
CD42  1U_0201_6.3V6M  [C_0201]  163.59 39.45 270 top
CD43  1U_0201_6.3V6M  [C_0201]  161.75 39.47 270 top
CD44  1U_0201_6.3V6M  [C_0201]  169.17 31.35 90 top
CD45  1U_0201_6.3V6M  [C_0201]  162.67 39.46 270 top
CD46  1U_0201_6.3V6M  [C_0201]  160.82 39.47 270 top
CD47  1U_0201_6.3V6M  [C_0201]  170.43 42.28 0 top
CD48  1U_0201_6.3V6M  [C_0201]  173.3 41.19 90 top
CD49  220U_D7_2VM_R4.5M  [C_D7]  199.12 43.67 180 top
CD50  1U_0201_6.3V6M  [C_0201]  202.35 40.45 0 top
CD51  1U_0201_6.3V6M  [C_0201]  202.35 39.52 0 top
CD52  10U_0603_10V6M  [C_0603]  200.98 37.14 0 top
CD53  10U_0603_10V6M  [C_0603]  201.32 38.4 0 top
CD54  10U_0603_10V6M  [C_0603]  200.5 28.87 270 top
CD55  1U_0201_6.3V6M  [C_0201]  201.13 30.55 0 top
CD56  1U_0201_6.3V6M  [C_0201]  201.12 31.48 0 top
CD57  0.1U_0201_6.3V6K  [C_0201]  173.04 27.44 270 top
CD58  2.2U_0402_6.3V6M  [C_0402]  172.15 27.44 270 top
CD59  2.2U_0402_6.3V6M  [C_0402]  199.78 39.09 180 top
CD60  0.1U_0201_10V6K  [C_0201]  199.64 39.86 180 top
CD61  0.1U_0402_25V6  [C_0402]  143.07 31.44 180 top
CD62  0.022U_0402_16V7K  [C_0402]  169.36 27.67 90 top
CD63  10U_0603_10V6M  [C_0603]  125.31 31.41 270 top
CD66  10U_0603_10V6M  [C_0603]  201.77 28.87 270 top
CD69  1U_0201_6.3V6M  [C_0201]  124.17 31.44 270 top
CD70  1U_0201_6.3V6M  [C_0201]  124.17 33.03 90 top
CD71  1U_0201_6.3V6M  [C_0201]  199.95 31.48 180 top
CD72  1U_0201_6.3V6M  [C_0201]  199.95 30.59 180 top
CE3  2200P_0402_50V7K  [C_0402]  277.58 69.65 270 top
CE4  2200P_0402_50V7K  [C_0402]  288.62 81 0 top
CE8  .047U_0402_16V7K  [C_0402]  284.87 88.51 270 top
CE10  0.1U_0201_10V6K  [C_0201]  266.03 72.71 270 top
CE11  0.1U_0201_10V6K  [C_0201]  270.01 74.52 270 top
CE12  2.2U_0402_6.3V6M  [C_0402]  267.54 74.94 270 top
CE13  0.1U_0201_10V6K  [C_0201]  270.58 80.87 270 top
CE14  1U_0201_6.3V6M  [C_0201]  269.98 80.89 180 top
CE15  0.1U_0201_10V6K  [C_0201]  279.85 75.5 270 top
CE16  10U_0402_6.3V6M  [C_0402]  274.93 70.58 90 top
CE17  22U_0402_6.3V6M  [C_0402]  275.96 74.68 0 top
CE18  0.1U_0201_10V6K  [C_0201]  276.16 75.61 0 top
CE19  0.1U_0201_10V6K  [C_0201]  284.64 89.78 0 top
CE20  0.1U_0201_10V6K  [C_0201]  284.64 89.21 0 top
CE21  0.1U_0201_10V6K  [C_0201]  284.33 80.84 270 top
CE22  0.1U_0201_10V6K  [C_0201]  287.31 80.71 270 top
CE23  0.1U_0201_10V6K  [C_0201]  281.69 75.53 270 top
CE24  2200P_0402_50V7K  [C_0402]  270.4 82.54 270 top
CE25  0.1U_0201_10V6K  [C_0201]  282.56 92.03 90 top
CE26  2200P_0402_50V7K  [C_0402]  268.87 83.64 270 top
CE27  2200P_0402_50V7K  [C_0402]  269.62 84.32 45 top
CE28  10P_0402_50V8J  [C_0402]  269.56 77.1 270 top
CE29  10P_0402_50V8J  [C_0402]  269.56 77.96 90 top
CE30  1U_0201_6.3V6M  [C_0201]  273.99 97.31 180 top
CE31  1U_0201_6.3V6M  [C_0201]  280.93 75.53 270 top
CE32  10U_0402_6.3V6M  [C_0402]  189.19 81.67 270 bottom
CE35  100P_0402_50V8J  [C_0402]  120.14 78.39 0 top
CE36  0.1U_0201_10V6K  [C_0201]  177.64 98.16 0 bottom
CE37  100P_0402_50V8J  [C_0402]  14.1 26.97 90 bottom
CE38  0.1U_0402_25V6  [C_0402]  273.88 91.74 90 top
CE39  100P_0402_50V8J  [C_0402]  89.93 99.75 180 bottom
CE40  4700P_0402_25V7K  [C_0402]  279.53 95.83 270 top
CE46  100P_0402_50V8J  [C_0402]  208.62 40.76 180 bottom
CE47  4700P_0402_25V7K  [C_0402]  283.72 94.02 90 top
CE52  0.1U_0201_10V6K  [C_0201]  177.21 81.15 180 bottom
CE53  0.1U_0201_10V6K  [C_0201]  179.88 81.15 180 bottom
CE54  10P_0402_50V8J  [C_0402]  274.79 75.5 270 top
CE57  33P_0402_50V8J  [C_0402]  278.83 72.46 270 top
CE59  12P_0402_50V8J  [C_0402]  274.96 69.67 270 top
CE60  68P_0402_50V8J  [C_0402]  273.63 69.54 270 top
CE61  68P_0402_50V8J  [C_0402]  181.91 84.51 180 bottom
CE62  4700P_0402_25V7K  [C_0402]  274.83 72.43 90 top
CE63  1U_0201_6.3V6M  [C_0201]  273.75 67.09 270 top
CE64  0.1U_0402_25V6  [C_0402]  274.97 63.82 90 top
CE65  22P_0402_50V8J  [C_0402]  276.83 64.78 180 top
CE66  0.1U_0402_25V6  [C_0402]  286.27 82.53 0 top
CE67  0.1U_0402_25V6  [C_0402]  267.35 82.3 90 top
CE68  0.1U_0402_25V6  [C_0402]  285.44 72.56 90 top
CI1  100U_A_6.3VM_R70M  [C_A]  23.06 40.28 90 bottom
CI3  0.1U_0201_10V6K  [C_0201]  25.89 42.49 90 bottom
CI4  0.1U_0402_25V6  [C_0402]  25.03 42.53 0 top
CI5  0.1U_0402_25V6  [C_0402]  25.03 41.64 0 top
CI6  10U_0603_10V6M  [C_0603]  30.12 40.61 0 bottom
CI7  0.1U_0201_10V6K  [C_0201]  30.49 41.6 0 bottom
CI13  0.1U_0402_25V6  [C_0402]  292.9 81.9 180 top
CI14  100U_A_6.3VM_R70M  [C_A]  305.02 71.39 270 bottom
CI16  0.1U_0402_25V6  [C_0402]  292.9 80.88 180 top
CI17  0.1U_0201_10V6K  [C_0201]  296.6 79.29 90 top
CI19  0.1U_0201_10V6K  [C_0201]  290.87 76.89 270 top
CI31  100P_0402_50V8J  [C_0402]  290.92 77.76 90 top
CI32  150U_B2_6.3VM_R35M  [C_B2]  302.22 70.95 90 bottom
CI33  47U_0603_6.3V6M  [C_0603]  289.78 77.64 90 top
CI34  47U_0603_6.3V6M  [C_0603]  289.78 76.63 270 top
CI43  12P_0402_50V8J  [C_0402]  294.98 79.15 90 top
CI44  68P_0402_50V8J  [C_0402]  295.87 79.15 90 top
CI45  12P_0402_50V8J  [C_0402]  26.61 39.69 270 bottom
CI46  68P_0402_50V8J  [C_0402]  25.13 42.2 90 bottom
CI103  150U_B2_6.3VM_R35M  [C_B2-NPM]  23.06 40.59 270 bottom
CLIP1  -  [CLIP_0P8X7P0]  303.34 91.83 90 top
CLIP2  -  [CLIP_0P8X7P0]  298.34 83.23 0 top
CLIP3  -  [CLIP_0P8X7P0]  303.34 74.63 90 top
CLIP4  -  [CLIP_0P8X7P0]  303.74 91.83 270 bottom
CLIP5  -  [CLIP_0P8X7P0]  298.34 88.2 180 bottom
CLIP6  -  [CLIP_0P8X7P0]  303.74 74.63 270 bottom
CLIP7  -  [CLIP_0P8X7P0]  14.12 50.35 90 top
CLIP8  -  [CLIP_0P8X7P0]  19.12 41.75 0 top
CLIP9  -  [CLIP_0P8X7P0]  14.12 33.15 90 top
CLIP10  -  [CLIP_0P8X7P0]  13.72 50.35 270 bottom
CLIP11  -  [CLIP_0P8X7P0]  19.12 36.77 180 bottom
CLIP12  -  [CLIP_0P8X7P0]  13.72 33.15 270 bottom
CLIP13  EMIST_SUL-15A3M  [EMIST_SUL-15A3M_1P]  32.33 85.25 180 bottom
CLIP14  EMIST_SUL-15A3M  [EMIST_SUL-15A3M_1P]  36.73 65.85 270 bottom
CLIP15  EMIST_SUL-15A3M  [EMIST_SUL-15A3M_1P]  15.53 68.23 270 bottom
CLIP16  EMIST_SUL-15A3M  [EMIST_SUL-15A3M_1P]  30.61 49.05 180 bottom
CLIP17  -  [CLIP_14P1X2P6]  232.43 46.7 180 bottom
CMOS1  SHORT PADS~D  [SHORTPADS-NPM]  154.27 53.4 270 top
CN60  68P_0402_50V8J  [C_0402]  26.32 25.65 0 top
CN61  0.1U_0402_10V7K  [C_0402]  28.47 23.27 90 top
CN62  0.1U_0402_10V7K  [C_0402]  34.04 23.25 90 top
CN63  22U_0603_6.3V6M  [C_0603]  27.41 23.22 90 top
CN64  22U_0603_6.3V6M  [C_0603]  32.09 23.25 90 top
CN65  0.22U_0402_10V6K  [C_0402]  32.28 25.94 90 bottom
CN66  0.22U_0402_10V6K  [C_0402]  31.39 25.94 90 bottom
CN67  0.22U_0402_10V6K  [C_0402]  29.17 25.94 90 bottom
CN68  0.22U_0402_10V6K  [C_0402]  28.28 25.94 90 bottom
CN69  0.22U_0402_10V6K  [C_0402]  25.72 25.13 90 bottom
CN70  0.22U_0402_10V6K  [C_0402]  24.79 25.11 90 bottom
CN71  0.22U_0402_10V6K  [C_0402]  22.25 25.11 90 bottom
CN72  0.22U_0402_10V6K  [C_0402]  21.34 25.13 90 bottom
CN77  27P_0402_50V8J  [C_0402]  12.92 23.62 90 top
CN78  100P_0402_50V8J~D  [C_0402]  13.82 23.62 90 top
CN79  0.01U_0402_16V7K  [C_0402]  29.74 23.27 90 top
CN80  0.01U_0402_16V7K  [C_0402]  30.99 23.27 90 top
CN81  0.01U_0402_16V7K  [C_0402]  33.14 23.25 90 top
CN82  0.01U_0402_16V7K  [C_0402]  16 23.62 90 top
CN84  0.01U_0402_16V7K  [C_0402]  16.91 23.62 90 top
CN86  0.1U_0402_10V7K  [C_0402]  17.82 23.62 90 top
CN87  22U_0603_6.3V6M  [C_0603]  14.89 23.18 90 top
CR1  4.7U_0402_6.3V6M  [C_0402]  292.86 71.13 90 top
CR2  0.1U_0201_10V6K  [C_0201]  292.89 70.1 0 top
CR3  0.1U_0201_10V6K  [C_0201]  291.76 62.69 180 top
CR4  10U_0402_6.3V6M  [C_0402]  291.87 61.32 0 top
CR5  4.7U_0402_10V6M  [C_0402]  294.46 62.43 270 top
CR6  0.1U_0201_10V6K  [C_0201]  290.58 62.92 270 top
CR7  0.1U_0201_10V6K  [C_0201]  293.69 62.4 270 top
CR11  0.1U_0402_25V6  [C_0402]  285.26 64.9 0 top
CR12  0.1U_0402_25V6  [C_0402]  285.26 64.01 0 top
CR13  0.1U_0402_25V6  [C_0402]  287.57 64.4 45 top
CR14  0.1U_0402_25V6  [C_0402]  288.21 63.77 45 top
CR15  1U_0201_6.3V6M  [C_0201]  295.73 69.21 0 top
CR17  0.1U_0201_10V6K  [C_0201]  299.6 57.55 90 top
CR18  4.7U_0402_10V6M  [C_0402]  298.86 58.22 270 top
CR19  0.1U_0201_10V6K  [C_0201]  309.76 68.42 270 bottom
CR20  4.7U_0402_10V6M  [C_0402]  308.69 68.19 180 bottom
CR21  5P_0402_50V8C  [C_0402]  297.3 63.43 0 top
CR22  1U_0201_6.3V6M  [C_0201]  295.82 64.31 0 top
CR25  12P_0402_50V8J  [C_0402]  291.87 59.54 0 top
CR26  82P_0402_50V8J  [C_0402]  291.87 60.43 0 top
CR27  12P_0402_50V8J  [C_0402]  294.64 71.13 90 top
CR28  82P_0402_50V8J  [C_0402]  293.75 71.13 90 top
CT1  0.1U_0201_10V6K  [C_0201]  38.42 69.76 270 bottom
CT2  0.22U_0201_6.3V6M  [C_0201]  33.24 69.21 90 bottom
CT3  0.22U_0201_6.3V6M  [C_0201]  33.81 69.21 90 bottom
CT4  0.22U_0201_6.3V6M  [C_0201]  30.23 69.21 90 bottom
CT5  0.22U_0201_6.3V6M  [C_0201]  30.81 69.21 90 bottom
CT6  0.22U_0201_6.3V6M  [C_0201]  32.11 69.8 270 bottom
CT7  0.22U_0201_6.3V6M  [C_0201]  31.53 69.8 270 bottom
CT8  0.22U_0201_6.3V6M  [C_0201]  29.33 68.01 270 bottom
CT9  0.22U_0201_6.3V6M  [C_0201]  29.9 68.01 270 bottom
CT10  0.1U_0201_10V6K  [C_0201]  34.44 80.79 180 bottom
CT11  0.1U_0201_10V6K  [C_0201]  34.44 80.22 180 bottom
CT12  0.1U_0201_10V6K  [C_0201]  34.43 79.08 180 bottom
CT13  0.1U_0201_10V6K  [C_0201]  34.43 79.65 180 bottom
CT14  0.1U_0201_10V6K  [C_0201]  34.19 77.92 180 bottom
CT15  0.1U_0201_10V6K  [C_0201]  34.19 78.49 180 bottom
CT16  0.1U_0201_10V6K  [C_0201]  34.08 76.46 180 bottom
CT17  0.1U_0201_10V6K  [C_0201]  34.08 77.03 180 bottom
CT18  0.1U_0201_10V6K  [C_0201]  36.73 81.2 180 top
CT19  0.1U_0201_10V6K  [C_0201]  36.73 81.77 180 top
CT20  27P_0402_50V8J  [C_0402]  19.6 67.7 180 bottom
CT21  27P_0402_50V8J  [C_0402]  20.42 67.7 0 bottom
CT22  100P_0402_50V8J~D  [C_0402]  29.9 60.7 0 top
CT25  1U_0201_6.3V6M  [C_0201]  27.01 80.52 0 top
CT26  1U_0201_6.3V6M  [C_0201]  26.56 79.06 0 top
CT27  1U_0201_6.3V6M  [C_0201]  26.5 77.21 0 top
CT28  1U_0201_6.3V6M  [C_0201]  29.6 76.39 180 top
CT29  1U_0201_6.3V6M  [C_0201]  31.1 77.43 90 top
CT30  1U_0201_6.3V6M  [C_0201]  25.91 79.89 90 top
CT31  1U_0201_6.3V6M  [C_0201]  31.04 76.2 270 top
CT32  1U_0201_6.3V6M  [C_0201]  28.92 75.24 0 top
CT33  1U_0201_6.3V6M  [C_0201]  27.82 75.97 90 top
CT34  1U_0201_6.3V6M  [C_0201]  27.12 76.04 90 top
CT35  1U_0201_6.3V6M  [C_0201]  28.07 73.06 270 top
CT36  1U_0201_6.3V6M  [C_0201]  27.5 73.06 270 top
CT37  1U_0201_6.3V6M  [C_0201]  27.07 74.61 0 top
CT38  1U_0201_6.3V6M  [C_0201]  28.31 77.76 270 top
CT39  1U_0201_6.3V6M  [C_0201]  27.78 78.48 180 top
CT40  1U_0201_6.3V6M  [C_0201]  28.97 79.06 0 top
CT41  1U_0201_6.3V6M  [C_0201]  28.98 79.73 0 top
CT42  1U_0201_6.3V6M  [C_0201]  23.87 80.35 180 top
CT43  1U_0201_6.3V6M  [C_0201]  24.21 79.13 180 top
CT44  10U_0402_6.3V6M  [C_0402]  18.99 82.91 90 bottom
CT45  10U_0402_6.3V6M  [C_0402]  18.1 82.91 90 bottom
CT46  10U_0402_6.3V6M  [C_0402]  21.27 84.65 315 top
CT47  10U_0402_6.3V6M  [C_0402]  19.88 82.91 90 bottom
CT48  1U_0201_6.3V6M  [C_0201]  24.63 76.87 270 top
CT49  1U_0201_6.3V6M  [C_0201]  22.68 77.84 90 top
CT50  1U_0201_6.3V6M  [C_0201]  22.04 77.84 90 top
CT51  1U_0201_6.3V6M  [C_0201]  21.47 77.84 90 top
CT52  1U_0201_6.3V6M  [C_0201]  20.83 77.84 90 top
CT53  1U_0201_6.3V6M  [C_0201]  22.04 77.21 270 top
CT54  1U_0201_6.3V6M  [C_0201]  22.68 77.21 270 top
CT55  47U_0603_6.3V6M  [C_0603]  16.89 89.12 270 bottom
CT56  47U_0603_6.3V6M  [C_0603]  18.16 89.12 270 bottom
CT57  47U_0603_6.3V6M  [C_0603]  19.43 89.12 270 bottom
CT59  10U_0402_6.3V6M  [C_0402]  26.4 73.14 270 top
CT60  10U_0402_6.3V6M  [C_0402]  25.51 73.13 270 top
CT61  1U_0201_6.3V6M  [C_0201]  23.79 75.92 180 top
CT62  1U_0201_6.3V6M  [C_0201]  24.7 77.66 0 top
CT63  1U_0201_6.3V6M  [C_0201]  24.01 73.18 270 top
CT64  1U_0201_6.3V6M  [C_0201]  25.24 75.7 180 top
CT67  1U_0201_6.3V6M  [C_0201]  37.81 76 0 top
CT68  47U_0603_6.3V6M  [C_0603]  37.51 76.98 0 top
CT69  47U_0603_6.3V6M  [C_0603]  37.5 78.3 0 top
CT70  0.1U_0201_10V6K  [C_0201]  30.74 46.68 270 top
CT71  2.2U_0402_16V6K  [C_0402]  33.05 53.36 270 bottom
CT72  2.2U_0402_16V6K  [C_0402]  34.74 55.32 270 top
CT73  2.2U_0402_16V6K  [C_0402]  27.76 54.26 270 bottom
CT74  10U_0402_6.3V6M  [C_0402]  34.16 53.46 0 bottom
CT75  22U_0603_10V6M  [C_0603]  35.06 67.68 180 bottom
CT76  22U_0603_10V6M  [C_0603]  35.06 63.87 180 bottom
CT77  22U_0603_10V6M  [C_0603]  35.06 66.41 180 bottom
CT78  22U_0603_10V6M  [C_0603]  35.06 65.14 180 bottom
CT80  0.1U_0201_10V6K  [C_0201]  28.54 50.92 90 bottom
CT81  0.1U_0201_10V6K  [C_0201]  27.97 50.92 90 bottom
CT82  1U_0603_50V6K  [C_0603]  28.72 63.94 90 bottom
CT83  1U_0201_6.3V6M  [C_0201]  29.58 54.18 270 bottom
CT84  10U_0402_6.3V6M  [C_0402]  31.08 53.47 270 bottom
CT85  220P_0402_50V8J  [C_0402]  26.22 62.41 0 bottom
CT86  220P_0402_50V8J  [C_0402]  25.86 60.7 180 bottom
CT87  0.22U_0402_16V7K  [C_0402]  29.05 58.98 90 top
CT88  0.1U_0201_10V6K  [C_0201]  23.63 88.93 270 bottom
CT89  1U_0201_10V6M  [C_0201]  25.56 89.72 0 bottom
CT90  1U_0201_10V6M  [C_0201]  23.06 88.93 270 bottom
CT91  2.2U_0402_10V6M  [C_0402]  25.08 90.54 0 bottom
CT92  0.1U_0201_10V6K  [C_0201]  25.24 91.43 0 bottom
CT94  1U_0603_25V6K  [C_0603]  22.82 28.87 90 bottom
CT95  0.22U_0201_25V6K  [C_0201]  13.19 81.85 180 bottom
CT96  0.22U_0201_25V6K  [C_0201]  13.19 82.48 180 bottom
CT97  0.22U_0201_25V6K  [C_0201]  12.43 89.68 180 top
CT98  0.22U_0201_25V6K  [C_0201]  12.43 89.05 180 top
CT99  0.47U_0201_25V  [C_0201]  10.3 83.75 0 bottom
CT100  0.47U_0201_25V  [C_0201]  10.65 87.36 180 bottom
CT101  0.47U_0201_25V  [C_0201]  10.07 86.8 0 bottom
CT102  0.47U_0201_25V  [C_0201]  10.88 84.34 180 bottom
CT123  0.22U_0201_6.3V6M  [C_0201]  28.59 69.19 90 bottom
CT124  0.22U_0201_6.3V6M  [C_0201]  28.02 69.19 90 bottom
CT125  0.22U_0201_6.3V6M  [C_0201]  26.26 69.19 90 bottom
CT126  0.22U_0201_6.3V6M  [C_0201]  26.83 69.19 90 bottom
CT127  0.22U_0201_6.3V6M  [C_0201]  27.15 68 270 bottom
CT128  0.22U_0201_6.3V6M  [C_0201]  27.72 68 270 bottom
CT129  0.22U_0201_6.3V6M  [C_0201]  25.78 68 270 bottom
CT130  0.22U_0201_6.3V6M  [C_0201]  25.21 68 270 bottom
CT168  0.1U_0201_10V6K  [C_0201]  34.13 73.52 180 bottom
CT169  0.1U_0201_10V6K  [C_0201]  36.94 73.08 180 top
CT170  0.1U_0201_10V6K  [C_0201]  34.14 71.81 180 bottom
CT171  0.1U_0201_10V6K  [C_0201]  34.12 74.15 180 bottom
CT172  0.1U_0201_10V6K  [C_0201]  34.12 74.73 180 bottom
CT173  0.1U_0201_10V6K  [C_0201]  34.14 72.38 180 bottom
CT174  0.1U_0201_10V6K  [C_0201]  34.13 72.95 180 bottom
CT175  0.1U_0201_10V6K  [C_0201]  36.94 72.45 180 top
CT176  0.1U_0201_10V6K  [C_0201]  34.06 75.88 180 bottom
CT177  0.1U_0201_10V6K  [C_0201]  34.06 75.31 180 bottom
CT189  12P_0402_50V8J  [C_0402]  12.54 93.7 90 bottom
CT190  82P_0402_50V8J  [C_0402]  13.43 93.7 90 bottom
CT193  1U_0201_10V6M  [C_0201]  18.73 31.44 180 bottom
CT201  1P_0201_50V8C  [C_0201]  20.64 53.04 90 bottom
CT202  1P_0201_50V8C  [C_0201]  20.64 56.85 90 bottom
CT203  1P_0201_50V8C  [C_0201]  20.61 55.07 90 bottom
CT204  1P_0201_50V8C  [C_0201]  20.64 58.76 90 bottom
CT237  0.1U_0201_10V6K  [C_0201]  40.27 68.15 90 bottom
CT326  0.33U_0201_25V6K  [C_0201]  13.19 81.85 180 top
CT327  0.33U_0201_25V6K  [C_0201]  13.19 82.48 180 top
CT328  0.33U_0201_25V6K  [C_0201]  12.43 89.68 180 bottom
CT329  0.33U_0201_25V6K  [C_0201]  12.43 89.05 180 bottom
CT359  100P_0201_25V8J  [C_0201]  25.24 92.07 0 bottom
CT360  0.1U_0201_10V6K  [C_0201]  26.68 45.68 90 top
CV1  0.1U_0402_25V6  [C_0402]  69.3 108.13 90 top
CV2  0.1U_0402_25V6  [C_0402]  70.32 108.13 90 top
CV3  0.1U_0402_25V6  [C_0402]  71.34 108.13 90 top
CV4  0.1U_0402_25V6  [C_0402]  72.35 108.13 90 top
CV5  0.1U_0402_25V6  [C_0402]  73.37 108.13 90 top
CV6  0.1U_0402_25V6  [C_0402]  74.38 108.13 90 top
CV11  0.1U_0603_50V7K  [C_0603]  65.3 107.65 180 top
CV12  0.1U_0201_10V6K  [C_0201]  73.88 111.33 90 top
CV13  1000P_0402_50V7K  [C_0402]  94.88 99.87 270 bottom
CV14  0.01U_0402_50V7K  [C_0402]  94.88 100.88 90 bottom
CV15  0.1U_0402_25V6  [C_0402]  92.4 101.21 0 bottom
CV16  10U_0402_10V6M  [C_0402]  102.62 101.91 270 bottom
CV17  0.01UF_0402_25V7K  [C_0402]  101.48 100.37 90 bottom
CV18  12P_0402_50V8J  [C_0402]  57.05 111.28 90 top
CV19  82P_0402_50V8J  [C_0402]  56.1 111.28 90 top
CV20  12P_0201_50V8J  [C_0201]  70.32 111.33 90 top
CV21  82P_0201_50V8J  [C_0201]  71.21 111.33 90 top
CV22  12P_0402_50V8J  [C_0402]  61.37 111.33 90 top
CV23  82P_0402_50V8J  [C_0402]  60.48 111.33 90 top
CV24  12P_0402_50V8J  [C_0402]  64.2 111.36 90 top
CV25  82P_0402_50V8J  [C_0402]  64.43 109.71 180 top
CV31  0.1U_0402_25V6  [C_0402]  19.91 52.97 180 bottom
CV32  0.1U_0402_25V6  [C_0402]  19.93 53.86 180 bottom
CV33  0.1U_0402_25V6  [C_0402]  19.91 56.74 180 bottom
CV34  0.1U_0402_25V6  [C_0402]  19.91 57.63 180 bottom
CV35  0.1U_0402_25V6  [C_0402]  19.9 54.95 180 bottom
CV36  0.1U_0402_25V6  [C_0402]  19.91 55.84 180 bottom
CV37  0.1U_0402_25V6  [C_0402]  19.04 58.61 0 bottom
CV38  0.1U_0402_25V6  [C_0402]  19.04 59.5 0 bottom
CV39  0.1U_0201_10V6K  [C_0201]  25.66 46.95 90 bottom
CV40  0.1U_0201_10V6K  [C_0201]  15.25 68.73 90 top
CV41  10U_0603_10V6M  [C_0603]  20.71 47.11 270 bottom
CV54  33P_0201_50V8J  [C_0201]  88.3 106.66 180 top
CV55  33P_0201_50V8J  [C_0201]  89.17 106.66 0 top
CV632  0.1U_0402_25V6  [C_0402]  87.83 103.23 0 top
CV633  2200P_0402_50V7K  [C_0402]  71.72 103.49 270 top
CV634  0.1U_0201_25V6K  [C_0201]  70.59 100.72 0 top
CV635  0.1U_0402_25V6K  [C_0402]  77.03 105.97 180 top
CV651  2200P_0402_50V7K  [C_0402]  89.24 105.04 270 top
CV652  0.1U_0201_25V6K  [C_0201]  86.14 103.05 0 top
CV750  120P_0402_50V8J  [C_0402]  59.59 111.33 90 top
CV751  100P_0201_50V8J  [C_0201]  72.1 111.33 90 top
CV752  100P_0201_50V8J  [C_0201]  72.99 111.33 90 top
CV753  120P_0402_50V8J  [C_0402]  64.43 108.74 180 top
CV754  120P_0402_50V8J  [C_0402]  55.21 111.28 90 top
CV755  47P_0402_50V8J  [C_0402]  77.48 101.1 270 top
CV756  100P_0402_50V8J~D  [C_0402]  78.43 101.1 270 top
CV757  27P_0201_25V8  [C_0201]  74.77 111.33 90 top
CV758  27P_0402_50V8J  [C_0402]  65.17 111.36 90 top
CZ2  0.1U_0201_10V6K  [C_0201]  54.45 111.19 90 top
CZ3  100P_0201_50V8J  [C_0201]  102.56 105.11 90 top
CZ12  0.1U_0402_25V6  [C_0402]  253.63 45.57 0 bottom
CZ13  0.1U_0402_25V6  [C_0402]  253.63 44.56 0 bottom
CZ17  .047U_0402_16V7K  [C_0402]  266.61 63.91 90 top
CZ18  .047U_0402_16V7K  [C_0402]  265.72 63.91 90 top
CZ19  33P_0402_50V8J  [C_0402]  284.06 61.27 270 top
CZ20  22U_0603_6.3V6M  [C_0603]  264.62 63.35 90 top
CZ21  33P_0402_50V8J  [C_0402]  283.91 63.93 90 top
CZ23  47P_0402_50V8J  [C_0402]  282.92 63.91 90 top
CZ24  100P_0402_50V8J  [C_0402]  283.17 61.27 270 top
CZ25  2000P_0402_50V7K  [C_0402]  267.5 63.91 90 top
CZ26  100U_B3_6.3VM_R45M  [C_B3]  268.16 58.93 0 top
CZ27  10U_0603_10V6M  [C_0603]  265.84 34.56 270 top
CZ28  0.01UF_0402_25V7K  [C_0402]  264.76 34.47 270 top
CZ29  0.01UF_0402_25V7K  [C_0402]  265.64 53.19 270 top
CZ30  0.1U_0201_10V6K  [C_0201]  264 34.31 270 top
CZ31  0.1U_0201_10V6K  [C_0201]  263.98 52.94 270 top
CZ32  4.7U_0402_10V6M  [C_0402]  264.73 53.19 270 top
CZ33  15P_0402_50V8J  [C_0402]  265.27 36.48 90 top
CZ34  15P_0402_50V8J  [C_0402]  266.15 36.48 90 top
CZ35  15P_0402_50V8J  [C_0402]  263.61 55.53 90 top
CZ36  15P_0402_50V8J  [C_0402]  264.5 55.53 90 top
CZ37  4.7U_0402_6.3V6M  [C_0402]  298.48 62.54 270 top
CZ38  47P_0402_50V8J  [C_0402]  293.77 56.45 180 top
CZ39  33P_0402_50V8J  [C_0402]  293.77 55.43 180 top
CZ40  33P_0402_50V8J  [C_0402]  293.79 57.51 180 top
CZ41  0.1U_0402_25V6  [C_0402]  299.41 62.55 270 top
CZ50  0.1U_0201_10V6K  [C_0201]  179.92 84.72 90 top
CZ51  0.1U_0201_10V6K  [C_0201]  185.6 84.69 0 top
CZ52  10U_0402_6.3V6M  [C_0402]  185.56 85.45 0 top
CZ53  0.1U_0201_10V6K  [C_0201]  183.39 77.93 90 bottom
CZ54  0.1U_0201_10V6K  [C_0201]  179.26 78.66 180 top
CZ55  10U_0603_10V6M  [C_0603]  184.22 78.23 0 bottom
CZ56  0.1U_0402_25V6  [C_0402]  182.44 79.1 90 bottom
CZ57  12P_0402_50V8J  [C_0402]  186.98 87.42 180 top
CZ58  68P_0402_50V8J  [C_0402]  186.98 88.31 180 top
CZ62  68P_0402_50V8J  [C_0402]  270.21 30.34 90 top
CZ63  68P_0402_50V8J  [C_0402]  270.21 29.48 270 top
CZ64  0.1U_0201_10V6K  [C_0201]  266.43 30.87 0 top
CZ66  0.1U_0201_10V6K  [C_0201]  259.47 32.42 180 top
CZ67  0.1U_0201_10V6K  [C_0201]  265.65 29.1 270 top
CZ68  0.1U_0201_10V6K  [C_0201]  266.98 32.16 90 top
CZ69  68P_0402_50V8J  [C_0402]  266.39 30.11 0 top
CZ71  68P_0402_50V8J  [C_0402]  259.37 33.18 180 top
CZ72  68P_0402_50V8J  [C_0402]  266.41 29.14 270 top
CZ73  68P_0402_50V8J  [C_0402]  267.98 32.18 90 top
CZ75  10U_0402_6.3V6M  [C_0402]  179.16 84.68 90 top
CZ80  10P_0402_50V8J  [C_0402]  250.08 28.78 0 top
CZ81  10P_0402_50V8J  [C_0402]  253.96 28.95 180 top
CZ82  0.1U_0201_10V6K  [C_0201]  178.4 53.23 270 top
CZ83  68P_0402_50V8J  [C_0402]  249.33 33.08 270 top
CZ84  68P_0402_50V8J  [C_0402]  245.05 34.08 90 bottom
CZ85  68P_0402_50V8J  [C_0402]  247.29 34.13 90 bottom
CZ86  68P_0402_50V8J  [C_0402]  248.18 34.13 90 bottom
CZ87  68P_0402_50V8J  [C_0402]  249.89 34.13 90 bottom
CZ88  68P_0402_50V8J  [C_0402]  251 30.58 270 top
CZ89  68P_0402_50V8J  [C_0402]  253.05 30.74 270 top
CZ90  0.1U_0201_10V6K  [C_0201]  250.13 32.99 270 top
CZ91  0.1U_0201_10V6K  [C_0201]  247.28 32.21 90 top
CZ92  0.1U_0201_10V6K  [C_0201]  247.08 30.13 270 top
CZ93  0.1U_0201_10V6K  [C_0201]  309.4 69.48 90 top
CZ94  0.1U_0201_10V6K  [C_0201]  174.06 110.76 90 top
CZ100  1U_0201_6.3V6M  [C_0201]  149.02 111.16 90 top
CZ101  0.1U_0201_10V6K  [C_0201]  148.86 107.73 0 top
CZ102  1U_0201_6.3V6M  [C_0201]  143.29 47.06 270 top
CZ105  1U_0201_6.3V6M  [C_0201]  144.16 111.08 90 top
CZ106  0.1U_0201_10V6K  [C_0201]  143.96 107.4 90 top
CZ109  470P_0402_50V7K  [C_0402]  258.72 56.69 180 top
CZ112  0.1U_0201_10V6K  [C_0201]  178.72 92.54 180 top
CZ113  100P_0402_50V8J  [C_0402]  178.66 93.83 180 top
CZ114  1000P_0402_50V7K  [C_0402]  178.66 94.84 180 top
CZ115  0.1U_0201_10V6K  [C_0201]  178.75 95.73 180 top
CZ116  0.1U_0201_10V6K  [C_0201]  268.31 40.79 270 top
CZ117  470P_0402_50V7K  [C_0402]  267.11 40.7 270 top
CZ118  470P_0402_50V7K  [C_0402]  266.03 40.7 270 top
CZ119  0.1U_0201_10V6K  [C_0201]  259.76 57.59 180 top
CZ120  0.1U_0201_10V6K  [C_0201]  293.36 23.94 90 top
CZ121  470P_0402_50V7K  [C_0402]  294.76 24.03 90 top
CZ122  0.1U_0201_10V6K  [C_0201]  265.27 40.79 270 top
CZ124  2200P_0402_50V7K  [C_0402]  260.5 56.69 180 top
CZ125  0.1U_0201_10V6K  [C_0201]  293.1 53.56 90 top
CZ126  220P_0402_50V7K  [C_0402]  293.86 53.65 90 top
CZ127  1000P_0402_50V7K  [C_0402]  295.26 53.52 90 top
CZ128  0.1U_0201_10V6K  [C_0201]  296.02 53.44 90 top
CZ150  0.1U_0402_10V7K  [C_0402]  239.92 42.98 0 top
CZ151  0.1U_0402_10V7K  [C_0402]  239.92 43.95 0 top
CZ152  0.22U_0402_10V6K  [C_0402]  239.92 45.19 0 top
CZ153  0.22U_0402_10V6K  [C_0402]  239.92 46.21 0 top
CZ154  0.01U_0402_16V7K  [C_0402]  247.15 43.57 0 top
CZ155  .1U_0402_16V7K  [C_0402]  246.77 44.49 0 top
CZ156  10U_0402_10V6M  [C_0402]  242.97 47.68 180 top
CZ197  470P_0402_50V7K  [C_0402]  294.51 19.1 270 top
CZ198  100P_0402_50V8J  [C_0402]  270 61.02 0 top
CZ200  0.1U_0402_25V6K  [C_0402]  310.28 94.37 270 bottom
CZ202  0.1U_0201_10V6K  [C_0201]  58.85 111.47 90 top
CZ204  100P_0402_50V8J~D  [C_0402]  267.04 36.48 90 top
CZ205  100P_0402_50V8J~D  [C_0402]  266.93 34.49 270 top
CZ206  27P_0402_50V8J  [C_0402]  265.52 55.53 90 top
CZ207  27P_0402_50V8J  [C_0402]  266.41 55.53 90 top
CZ210  0.1U_0402_25V6  [C_0402]  278.47 53.37 90 top
CZ211  0.1U_0402_25V6  [C_0402]  279.49 53.37 90 top
CZ218  2.2U_0603_10V6K  [C_0603]  298.38 8.13 270 top
CZ220  0.1U_0402_25V6K  [C_0402]  50.51 106.86 270 top
CZ227  120P_0402_50V8  [C_0402]  305.42 107.04 90 top
CZ228  120P_0402_50V8  [C_0402]  303.84 106.98 90 top
CZ229  120P_0402_50V8  [C_0402]  304.31 96.64 180 top
CZ230  120P_0402_50V8  [C_0402]  304.73 98.57 90 top
CZ233  100P_0201_25V8J  [C_0201]  303.18 95.87 270 top
